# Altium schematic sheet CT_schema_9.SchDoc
size 287 x 160 mm
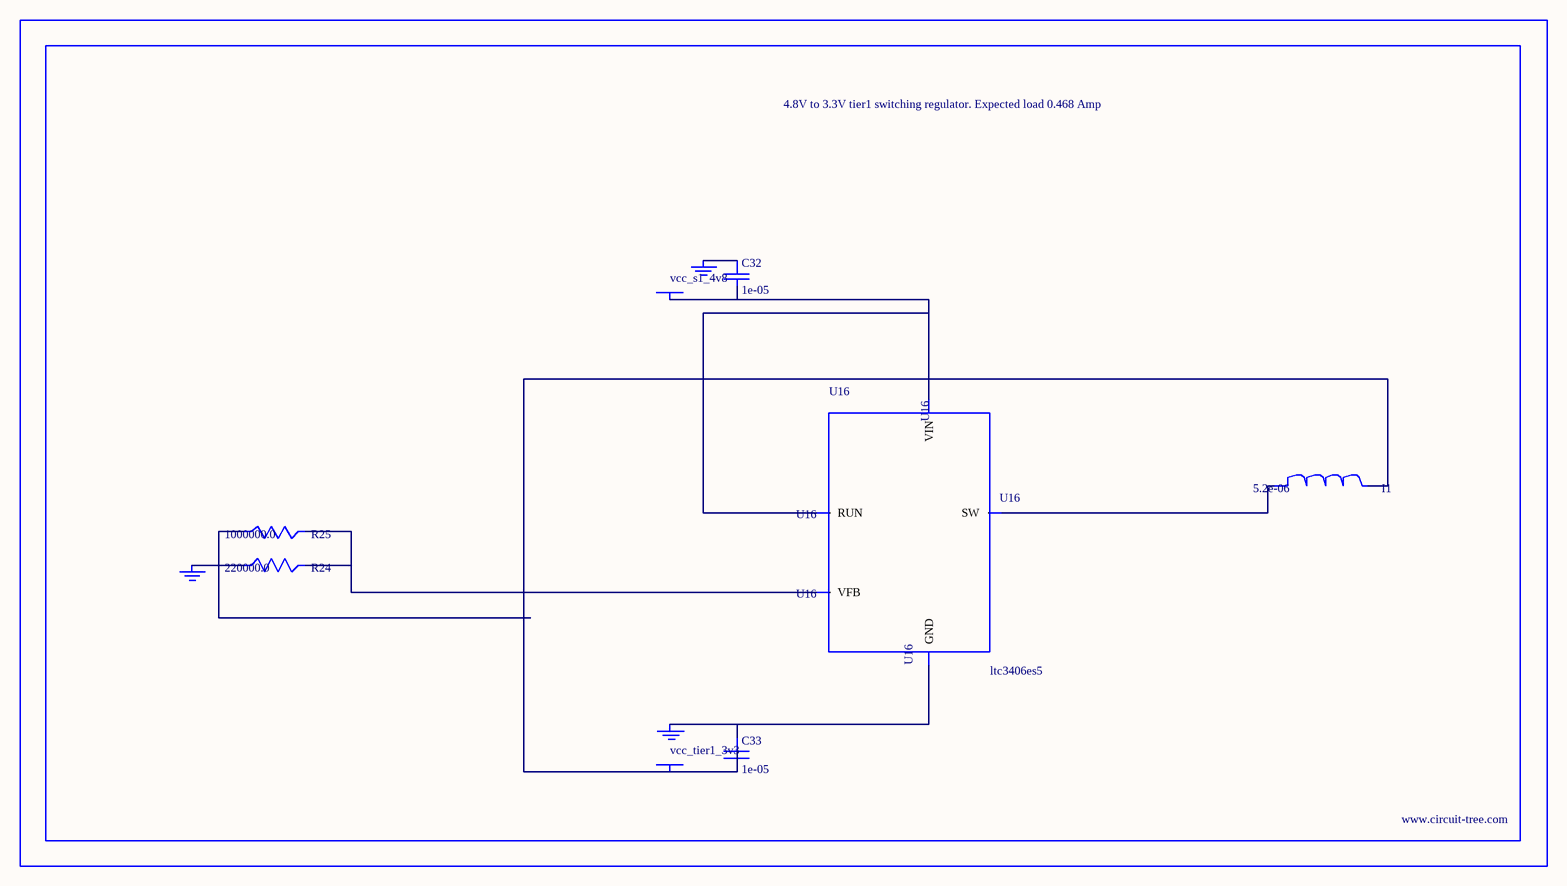
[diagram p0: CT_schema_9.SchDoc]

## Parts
BORDER8  (no value)
C32  1e-05  [C0805]
C33  1e-05  [C0805]
GND_INSTANCE_8_0  (no value)
GND_INSTANCE_8_1  (no value)
GND_INSTANCE_8_2  (no value)
I1  5.2e-06  [DR1040]
POWER_INSTANCE_8_0  vcc_tier1_3v3
POWER_INSTANCE_8_1  vcc_s1_4v8
R24  220000.0  [R0603]
R25  1000000.0  [R0603]
U16  ltc3406es5  [TSOT-23-5]

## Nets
NetC32_1: C32.1 GND_INSTANCE_8_1.0(GND)
NetC32_2: C32.2 POWER_INSTANCE_8_1.0(PWR) U16.1(RUN) U16.4(VIN)
NetC33_1: C33.1 GND_INSTANCE_8_0.0(GND) U16.2(GND)
NetC33_2: C33.2 I1.2 POWER_INSTANCE_8_0.0(PWR) R25.1
NetGND_INSTANCE_8_2_0: GND_INSTANCE_8_2.0(GND) R24.1
NetI1_1: I1.1 U16.3(SW)
NetR24_2: R24.2 R25.2 U16.5(VFB)

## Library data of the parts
BORDER8 = BORDER_PAGE8
C32 C33 = C0805C106K8RACTU
GND_INSTANCE_8_0-GND_INSTANCE_8_2 = GND
I1 = DR1040-5R2-R
POWER_INSTANCE_8_0 POWER_INSTANCE_8_1 = PWR
R24 = RC0603JR-07220KL
R25 = RC0603JR-071ML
